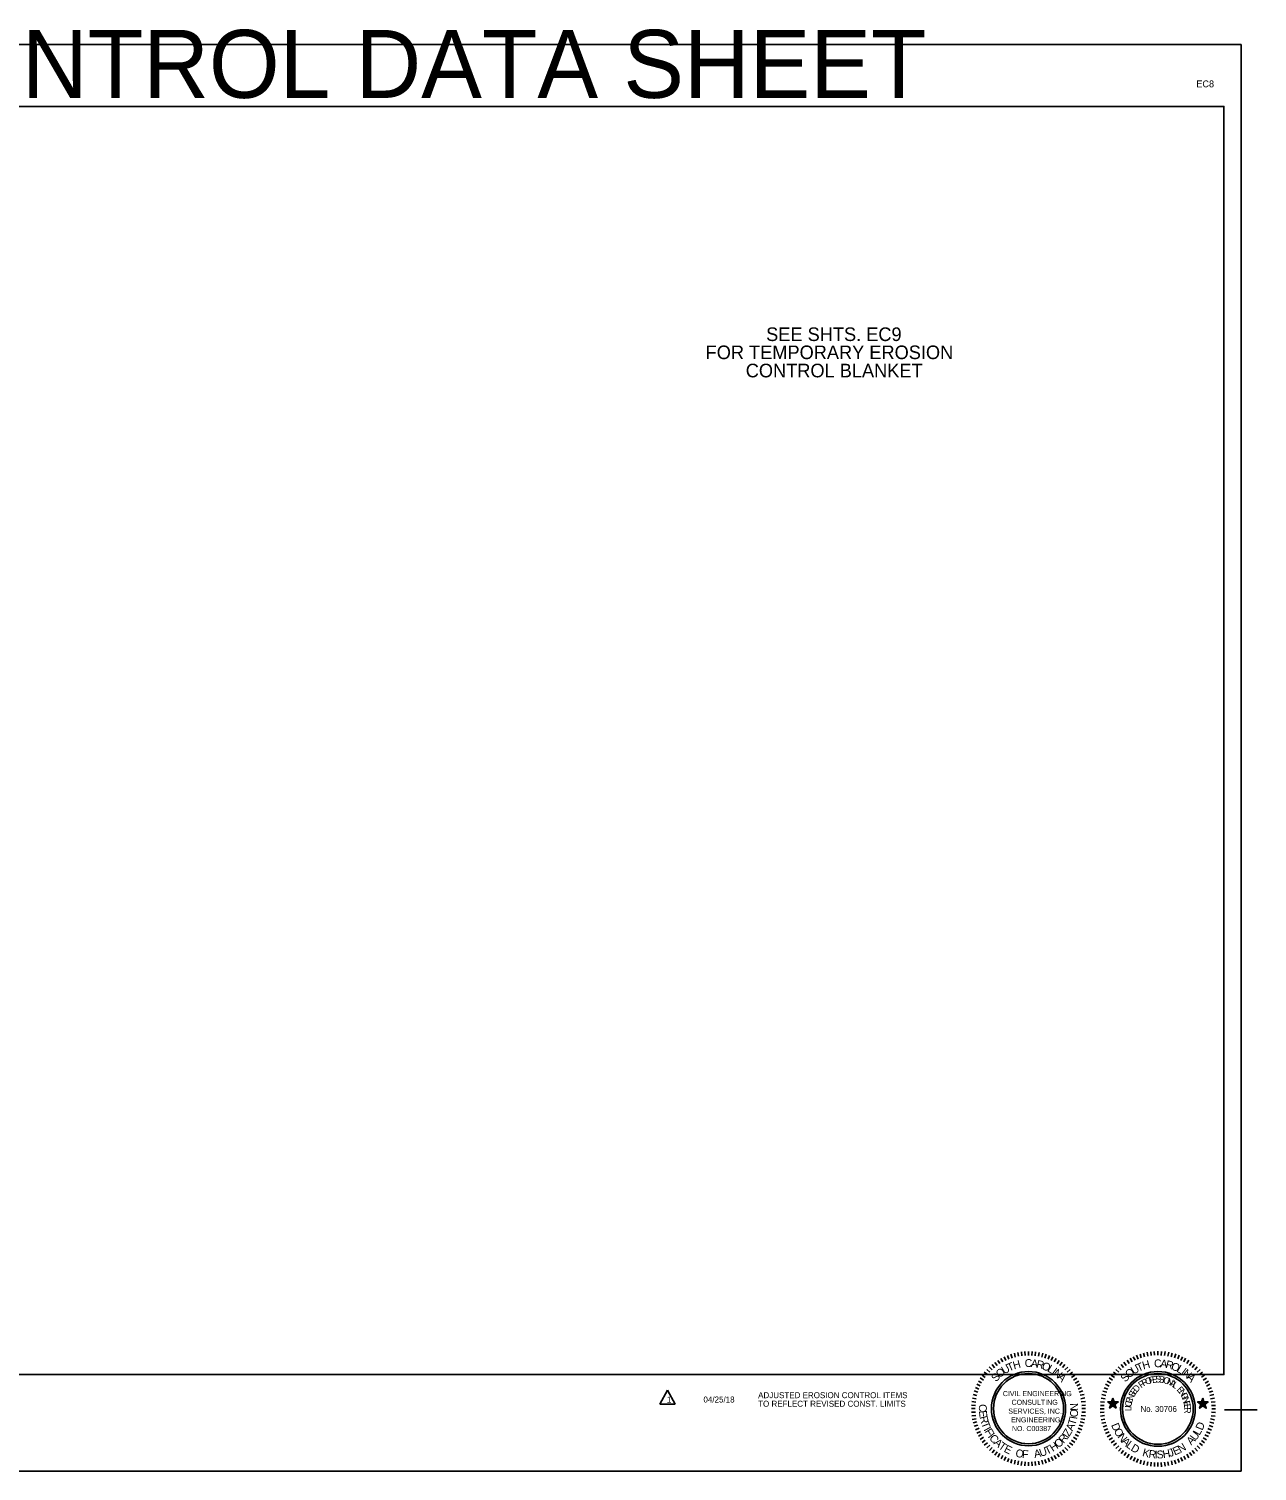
# Model space of a CAD drawing. Extents: x 260980 to 265883, y 322333 to 323618.
# Drawn here: x 261883 to 262786, y 322333 to 323393 of the extents above; entities that cross this region are included whole.
import ezdxf

# ---------------------------------------------------------------- set-up
doc = ezdxf.new("R2010")
doc.units = 0
for name, color, linetype in [('Level 23', 7, 'Continuous'), ('Level 3', 7, 'Continuous'), ('Level 4', 7, 'Continuous'), ('Level 8', 7, 'Continuous'), ('RD_SHT_SEAL_KA', 7, 'Continuous'), ('RD_SHT_TX', 7, 'Continuous')]:
    doc.layers.add(name, color=color, linetype=linetype)

msp = doc.modelspace()

# ---------------------------------------------------------------- linework, layer by layer
at = {"layer": 'Level 23'}
msp.add_lwpolyline([(261111.1, 323336.4), (262761.5, 323336.4), (262761.5, 322403.8), (261111.1, 322403.8)], close=True, dxfattribs=at)
at = {"layer": 'Level 3'}
for p, q in [((261099.2, 323381.9), (262774.2, 323381.9)), ((262774.2, 322332.8), (262774.2, 323381.9)), ((261099.2, 322332.9), (262774.2, 322332.9))]:
    msp.add_line(p, q, dxfattribs=at)
msp.add_lwpolyline([(261111.1, 322403.8), (262761.5, 322403.8), (262761.5, 323336.4), (261111.1, 323336.4)], close=True, dxfattribs=at)
at = {"layer": 'Level 4'}
msp.add_line((262762, 322377.8), (262786, 322377.8), dxfattribs=at)
at = {"layer": 'RD_SHT_SEAL_KA'}
for p, q in [((262600, 322416.8), (262601.2, 322414.2)), ((262602.4, 322417.9), (262603.5, 322415.2)), ((262604.9, 322418.8), (262605.8, 322416)), ((262607.5, 322419.5), (262608.1, 322416.7)), ((262610.1, 322420.2), (262610.5, 322417.3)), ((262612.7, 322420.5), (262613, 322417.7)), ((262615.3, 322420.8), (262615.4, 322417.9)), ((262617.9, 322420.9), (262617.9, 322418)), ((262620.6, 322420.8), (262620.4, 322417.9)), ((262623.1, 322420.5), (262622.8, 322417.7)), ((262625.7, 322420.1), (262625.3, 322417.4)), ((262628.4, 322419.5), (262627.6, 322416.7)), ((262630.9, 322418.8), (262630, 322416)), ((262633.3, 322417.9), (262632.4, 322415.2)), ((262635.8, 322416.8), (262634.6, 322414.2)), ((262692.5, 322415.8), (262694, 322413.2)), ((262694.9, 322417), (262696.2, 322414.4)), ((262697.4, 322418.1), (262698.5, 322415.3)), ((262699.9, 322418.9), (262700.8, 322416.2)), ((262702.4, 322419.7), (262703.1, 322416.9)), ((262705.1, 322420.3), (262705.6, 322417.4)), ((262707.7, 322420.6), (262708.1, 322417.8)), ((262710.3, 322420.9), (262710.5, 322418.1)), ((262713, 322421), (262713, 322418.2)), ((262715.6, 322420.9), (262715.4, 322417.9)), ((262718.3, 322420.7), (262717.9, 322417.8)), ((262721, 322420.3), (262720.4, 322417.5)), ((262723.6, 322419.7), (262722.8, 322416.9)), ((262726.1, 322419), (262725.2, 322416.2)), ((262728.6, 322418.1), (262727.6, 322415.4)), ((262731, 322417), (262729.8, 322414.3)), ((262733.4, 322415.8), (262732, 322413.3)), ((262585.4, 322405.6), (262587.7, 322403.8)), ((262587.3, 322407.5), (262589.4, 322405.6)), ((262589, 322409.5), (262591.1, 322407.4)), ((262591.1, 322411.3), (262592.9, 322408.9)), ((262593.2, 322412.8), (262594.8, 322410.6)), ((262595.4, 322414.3), (262596.9, 322411.9)), ((262597.6, 322415.7), (262599, 322413.1)), ((262638.1, 322415.7), (262636.7, 322413.2)), ((262640.5, 322414.2), (262638.9, 322411.8)), ((262642.6, 322412.9), (262640.9, 322410.5)), ((262644.7, 322411.2), (262642.9, 322409)), ((262646.7, 322409.4), (262644.7, 322407.4)), ((262648.6, 322407.6), (262646.4, 322405.6)), ((262650.3, 322405.6), (262648.1, 322403.8)), ((262680.3, 322405.6), (262682.5, 322403.8)), ((262682.1, 322407.5), (262684.2, 322405.6)), ((262683.9, 322409.5), (262686, 322407.4)), ((262685.9, 322411.3), (262687.8, 322409)), ((262688, 322412.9), (262689.8, 322410.6)), ((262690.3, 322414.4), (262691.8, 322412)), ((262735.8, 322414.4), (262734.2, 322412)), ((262737.9, 322412.9), (262736.3, 322410.5)), ((262740, 322411.3), (262738.2, 322409.1)), ((262742, 322409.5), (262740.1, 322407.4)), ((262744, 322407.6), (262741.8, 322405.6)), ((262745.7, 322405.6), (262743.5, 322403.8)), ((262579.8, 322396.7), (262582.4, 322395.5)), ((262581.1, 322399), (262583.4, 322397.7)), ((262582.3, 322401.4), (262584.9, 322399.8)), ((262583.9, 322403.5), (262586.1, 322401.8)), ((262651.9, 322403.5), (262649.6, 322401.8)), ((262653.4, 322401.3), (262651, 322399.8)), ((262654.9, 322399.1), (262652.2, 322397.6)), ((262655.9, 322396.7), (262653.4, 322395.5)), ((262674.6, 322396.7), (262677.2, 322395.4)), ((262675.8, 322399), (262678.4, 322397.6)), ((262677.2, 322401.4), (262679.7, 322399.8)), ((262678.6, 322403.5), (262681.1, 322401.8)), ((262747.3, 322403.5), (262745, 322401.9)), ((262748.8, 322401.3), (262746.4, 322399.8)), ((262750.2, 322399), (262747.7, 322397.6)), ((262751.3, 322396.7), (262748.8, 322395.4)), ((262576.1, 322384), (262579.1, 322383.6)), ((262576.6, 322386.6), (262579.4, 322386.1)), ((262577.2, 322389.2), (262579.9, 322388.4)), ((262577.9, 322391.8), (262580.7, 322390.9)), ((262578.8, 322394.3), (262581.4, 322393.2)), ((262656.9, 322394.3), (262654.3, 322393.2)), ((262657.9, 322391.8), (262655.2, 322390.9)), ((262658.7, 322389.2), (262655.8, 322388.6)), ((262659.2, 322386.7), (262656.4, 322386.1)), ((262659.7, 322384.1), (262656.7, 322383.7)), ((262671.3, 322386.5), (262674.2, 322386)), ((262671.9, 322389.1), (262674.7, 322388.4)), ((262672.6, 322391.7), (262675.4, 322390.8)), ((262673.6, 322394.2), (262676.3, 322393.1)), ((262752.5, 322394.2), (262749.8, 322393.2)), ((262753.4, 322391.7), (262750.6, 322390.8)), ((262754.1, 322389.2), (262751.3, 322388.5)), ((262754.7, 322386.6), (262751.8, 322386)), ((262575.9, 322376.1), (262578.8, 322376.3)), ((262576, 322381.3), (262578.8, 322381.2)), ((262576, 322378.8), (262578.7, 322378.8)), ((262576.2, 322373.5), (262579.1, 322373.8)), ((262659.7, 322373.5), (262656.7, 322373.8)), ((262659.9, 322381.4), (262657, 322381.2)), ((262659.9, 322376.1), (262657, 322376.3)), ((262659.9, 322378.8), (262657.1, 322378.8)), ((262670.6, 322378.6), (262673.5, 322378.6)), ((262670.6, 322375.9), (262673.5, 322376.1)), ((262670.7, 322381.2), (262673.6, 322381.1)), ((262670.9, 322383.9), (262673.8, 322383.6)), ((262670.9, 322373.2), (262673.8, 322373.7)), ((262755.2, 322383.9), (262752.2, 322383.6)), ((262755, 322373.3), (262752.2, 322373.6)), ((262755.3, 322381.2), (262752.5, 322381.1)), ((262755.3, 322376), (262752.5, 322376.2)), ((262755.4, 322378.6), (262752.6, 322378.6)), ((262576.5, 322370.9), (262579.4, 322371.4)), ((262577.2, 322368.3), (262579.9, 322369)), ((262577.9, 322365.8), (262580.6, 322366.6)), ((262578.8, 322363.2), (262581.5, 322364.4)), ((262657, 322363.3), (262654.3, 322364.4)), ((262657.9, 322365.8), (262655.1, 322366.6)), ((262658.7, 322368.3), (262655.9, 322369)), ((262659.2, 322370.8), (262656.3, 322371.4)), ((262671.3, 322370.6), (262674.1, 322371.1)), ((262671.9, 322368), (262674.7, 322368.7)), ((262672.7, 322365.5), (262675.4, 322366.4)), ((262673.5, 322363), (262676.3, 322364)), ((262752.5, 322363), (262749.7, 322364.1)), ((262753.3, 322365.5), (262750.6, 322366.4)), ((262754.1, 322368.1), (262751.3, 322368.8)), ((262754.7, 322370.6), (262751.8, 322371.2)), ((262579.8, 322360.8), (262582.5, 322362.1)), ((262581.1, 322358.5), (262583.5, 322360)), ((262582.4, 322356.2), (262584.9, 322357.8)), ((262583.9, 322353.9), (262586.1, 322355.7)), ((262585.4, 322352), (262587.7, 322353.7)), ((262650.4, 322351.9), (262648.1, 322353.7)), ((262651.9, 322353.9), (262649.6, 322355.7)), ((262653.5, 322356.1), (262650.9, 322357.7)), ((262654.7, 322358.5), (262652.2, 322359.9)), ((262655.9, 322360.9), (262653.4, 322362.1)), ((262674.6, 322360.5), (262677.2, 322361.8)), ((262675.8, 322358.1), (262678.4, 322359.6)), ((262677.2, 322355.8), (262679.6, 322357.4)), ((262678.7, 322353.6), (262681, 322355.4)), ((262680.3, 322351.6), (262682.6, 322353.4)), ((262745.8, 322351.6), (262743.5, 322353.4)), ((262747.3, 322353.6), (262745, 322355.3)), ((262748.8, 322355.8), (262746.4, 322357.3)), ((262750.2, 322358.2), (262747.6, 322359.5)), ((262751.4, 322360.5), (262748.8, 322361.8)), ((262587.3, 322350), (262589.4, 322351.9)), ((262589.1, 322348.1), (262591.1, 322350.2)), ((262591.1, 322346.3), (262592.9, 322348.5)), ((262593.2, 322344.7), (262594.9, 322347)), ((262595.3, 322343.2), (262596.9, 322345.7)), ((262597.7, 322341.9), (262599, 322344.3)), ((262600, 322340.6), (262601.2, 322343.4)), ((262602.4, 322339.6), (262603.5, 322342.2)), ((262604.9, 322338.7), (262605.7, 322341.5)), ((262633.4, 322339.6), (262632.3, 322342.3)), ((262635.9, 322340.7), (262634.6, 322343.3)), ((262638.2, 322341.9), (262636.8, 322344.3)), ((262640.4, 322343.3), (262638.9, 322345.6)), ((262642.6, 322344.7), (262640.9, 322347)), ((262644.6, 322346.3), (262642.9, 322348.5)), ((262646.7, 322348.1), (262644.7, 322350.2)), ((262648.6, 322350), (262646.5, 322351.9)), ((262682.1, 322349.5), (262684.2, 322351.5)), ((262684, 322347.6), (262685.9, 322349.7)), ((262686, 322345.9), (262687.8, 322348.1)), ((262688.1, 322344.3), (262689.8, 322346.6)), ((262690.2, 322342.7), (262691.8, 322345.2)), ((262692.6, 322341.4), (262694, 322343.9)), ((262695, 322340.2), (262696.2, 322342.8)), ((262697.3, 322339.1), (262698.5, 322341.8)), ((262728.6, 322339.1), (262727.6, 322341.8)), ((262731.1, 322340.2), (262729.9, 322342.8)), ((262733.4, 322341.4), (262732, 322343.9)), ((262735.7, 322342.7), (262734.2, 322345.2)), ((262738, 322344.3), (262736.3, 322346.6)), ((262740, 322345.9), (262738.2, 322348.1)), ((262742.1, 322347.6), (262740.1, 322349.8)), ((262743.9, 322349.5), (262741.9, 322351.5)), ((262607.5, 322338), (262608.1, 322340.8)), ((262610, 322337.4), (262610.5, 322340.3)), ((262612.6, 322336.9), (262613, 322339.9)), ((262615.3, 322336.7), (262615.5, 322339.7)), ((262617.9, 322336.7), (262617.9, 322339.5)), ((262620.6, 322336.7), (262620.4, 322339.7)), ((262623.1, 322337), (262622.8, 322339.9)), ((262625.7, 322337.4), (262625.3, 322340.2)), ((262628.3, 322338), (262627.7, 322340.8)), ((262630.9, 322338.7), (262630, 322341.4)), ((262699.9, 322338.2), (262700.7, 322341)), ((262702.4, 322337.4), (262703.1, 322340.3)), ((262705, 322336.9), (262705.6, 322339.8)), ((262707.7, 322336.5), (262708.1, 322339.4)), ((262710.4, 322336.2), (262710.5, 322339.1)), ((262713, 322336.2), (262713, 322339.1)), ((262715.7, 322336.1), (262715.5, 322339.2)), ((262718.3, 322336.5), (262717.9, 322339.4)), ((262720.9, 322336.9), (262720.4, 322339.8)), ((262723.6, 322337.5), (262722.9, 322340.3)), ((262726.1, 322338.2), (262725.2, 322340.9))]:
    msp.add_line(p, q, dxfattribs=at)
for points in [[(262679.9, 322386.5), (262679, 322383.7), (262676.1, 322383.7), (262678.5, 322381.9), (262677.5, 322379.2), (262680, 322380.9), (262682.3, 322379.2), (262681.4, 322381.9), (262683.8, 322383.7), (262680.8, 322383.7)], [(262679.9, 322386.1), (262679.1, 322383.6), (262676.4, 322383.6), (262678.5, 322382), (262677.8, 322379.4), (262679.9, 322381.1), (262682, 322379.4), (262681.2, 322382), (262683.4, 322383.6), (262680.8, 322383.6)], [(262680, 322385.7), (262679.1, 322383.4), (262676.8, 322383.4), (262678.7, 322382), (262678, 322379.8), (262679.9, 322381.2), (262681.9, 322379.7), (262681.1, 322382.1), (262683.1, 322383.4), (262680.7, 322383.4)], [(262680, 322385.3), (262679.2, 322383.3), (262677.2, 322383.3), (262678.9, 322382.1), (262678.3, 322380.1), (262679.9, 322381.3), (262681.7, 322380.1), (262681.1, 322382.1), (262682.7, 322383.4), (262680.6, 322383.3)], [(262679.9, 322385), (262679.4, 322383.2), (262677.6, 322383.2), (262679, 322382.1), (262678.4, 322380.4), (262679.9, 322381.5), (262681.4, 322380.4), (262680.8, 322382.1), (262682.3, 322383.2), (262680.6, 322383.2)], [(262679.9, 322384.6), (262679.5, 322383.1), (262677.9, 322383.1), (262679.2, 322382.2), (262678.7, 322380.7), (262680, 322381.7), (262681.2, 322380.7), (262680.7, 322382.2), (262682, 322383), (262680.4, 322383.1)], [(262679.9, 322384.1), (262679.6, 322383), (262678.3, 322382.8), (262679.3, 322382.3), (262679, 322381.1), (262679.9, 322381.8), (262681, 322381), (262680.6, 322382.3), (262681.5, 322383), (262680.3, 322383)], [(262746.1, 322386.5), (262745.1, 322383.7), (262742.2, 322383.7), (262744.6, 322381.9), (262743.6, 322379.1), (262746.1, 322380.9), (262748.5, 322379.1), (262747.5, 322381.9), (262749.9, 322383.7), (262746.9, 322383.7)], [(262746, 322386.1), (262745.2, 322383.6), (262742.6, 322383.6), (262744.8, 322381.9), (262744, 322379.4), (262746.1, 322381), (262748.2, 322379.4), (262747.4, 322382), (262749.6, 322383.6), (262746.9, 322383.6)], [(262746.1, 322385.7), (262745.4, 322383.4), (262742.9, 322383.4), (262744.9, 322382), (262744.2, 322379.7), (262746.1, 322381.2), (262748, 322379.8), (262747.3, 322382), (262749.2, 322383.5), (262746.8, 322383.4)], [(262746, 322385.3), (262745.4, 322383.3), (262743.3, 322383.3), (262745.1, 322382.1), (262744.3, 322380.1), (262746.1, 322381.3), (262747.8, 322380.1), (262747.1, 322382.1), (262748.8, 322383.3), (262746.7, 322383.3)], [(262746, 322384.9), (262745.5, 322383.2), (262743.6, 322383.2), (262745.1, 322382.2), (262744.6, 322380.4), (262746, 322381.4), (262747.5, 322380.4), (262747, 322382.1), (262748.5, 322383.2), (262746.6, 322383.2)], [(262746.1, 322384.5), (262745.6, 322383.1), (262744, 322383.1), (262745.3, 322382.3), (262744.8, 322380.7), (262746.1, 322381.6), (262747.3, 322380.7), (262746.9, 322382.1), (262748, 322383.1), (262746.6, 322383.1)], [(262746.1, 322384.1), (262745.6, 322383), (262744.4, 322383), (262745.5, 322382.2), (262745.1, 322381.1), (262746.1, 322381.8), (262747.1, 322381), (262746.7, 322382.3), (262747.8, 322383), (262746.5, 322383)], [(262679.9, 322383.8), (262679.7, 322382.8), (262678.7, 322382.8), (262679.5, 322382.3), (262679.2, 322381.4), (262679.9, 322381.9), (262680.7, 322381.3), (262680.5, 322382.3), (262681.2, 322382.8), (262680.2, 322382.9)], [(262679.9, 322383.3), (262679.7, 322382.7), (262679, 322382.7), (262679.6, 322382.3), (262679.4, 322381.7), (262680, 322382.1), (262680.4, 322381.7), (262680.3, 322382.3), (262680.8, 322382.7), (262680.1, 322382.7)], [(262680, 322383), (262679.8, 322382.6), (262679.4, 322382.6), (262679.8, 322382.4), (262679.6, 322382), (262680, 322382.3), (262680.2, 322382), (262680.1, 322382.4), (262680.4, 322382.6), (262680.1, 322382.6)], [(262680, 322382.6), (262679.9, 322382.4), (262679.7, 322382.5), (262679.9, 322382.5), (262679.8, 322382.3), (262679.9, 322382.3), (262680, 322382.3), (262680, 322382.4), (262680.1, 322382.5), (262680, 322382.5)], [(262746.1, 322383.7), (262745.8, 322382.8), (262744.8, 322382.8), (262745.6, 322382.3), (262745.3, 322381.4), (262746.1, 322381.9), (262746.8, 322381.3), (262746.6, 322382.3), (262747.3, 322382.8), (262746.3, 322382.8)], [(262746.1, 322383.4), (262745.8, 322382.7), (262745.2, 322382.7), (262745.7, 322382.4), (262745.5, 322381.7), (262746.1, 322382), (262746.6, 322381.7), (262746.4, 322382.3), (262747, 322382.7), (262746.3, 322382.7)], [(262746, 322383), (262746, 322382.6), (262745.5, 322382.6), (262745.9, 322382.4), (262745.7, 322382), (262746.1, 322382.2), (262746.4, 322382), (262746.2, 322382.3), (262746.6, 322382.6), (262746.2, 322382.6)], [(262746.1, 322382.6), (262746.1, 322382.5), (262745.9, 322382.5), (262746, 322382.4), (262746, 322382.3), (262746, 322382.4), (262746.2, 322382.4), (262746.1, 322382.4), (262746.2, 322382.5), (262746.1, 322382.4)]]:
    msp.add_lwpolyline(points, close=True, dxfattribs=at)
for radius in [27.5, 26]:
    msp.add_circle((262713, 322378.6), radius, dxfattribs=at)
for major_axis in [(0, 27.3), (0, 25.8)]:
    msp.add_ellipse((262617.9, 322378.8), major_axis=major_axis, ratio=0.998589, dxfattribs=at)
at = {"layer": 'RD_SHT_TX'}
for p, q in [((262352.5, 322392.3), (262346.8, 322382.1)), ((262358.2, 322382.1), (262352.5, 322392.3)), ((262346.8, 322382.1), (262358.2, 322382.1))]:
    msp.add_line(p, q, dxfattribs=at)

# ---------------------------------------------------------------- texts
at = {"layer": 'Level 3'}
for s, height, p in [('EC8', 5, (262741.3, 323350.5)), ('SEE SHTS. EC9', 10, (262425, 323163.9)), ('FOR TEMPORARY EROSION', 10, (262380.5, 323150.6)), ('CONTROL BLANKET', 10, (262410, 323137.2))]:
    msp.add_text(s, height=height, dxfattribs=at).set_placement(p)
at = {"layer": 'Level 8'}
msp.add_text('EROSION CONTROL DATA SHEET', height=50, dxfattribs=at).set_placement((261450.7, 323342.7))
at = {"layer": 'RD_SHT_SEAL_KA'}
for s, height, rotation, p in [('O', 5.79, 39.0332, (262596.7, 322401.1)), ('U', 5.79, 30.8031, (262600.1, 322403.9)), ('T', 5.79, 23.2887, (262603.6, 322406)), ('H', 5.79, 15.7743, (262607.3, 322407.6)), ('C', 5.79, 0.6858, (262615.1, 322409.4)), ('A', 5.79, 352.8136, (262619.4, 322409.5)), ('R', 5.79, 345.657, (262623.2, 322409.1)), ('O', 5.79, 338.1426, (262627.1, 322408.1)), ('L', 5.79, 329.9125, (262631.2, 322406.5)), ('I', 5.79, 323.1138, (262634.4, 322404.7)), ('N', 5.79, 320.609, (262635.5, 322404)), ('O', 5.79, 39.0332, (262691.8, 322400.9)), ('U', 5.79, 30.8031, (262695.2, 322403.7)), ('T', 5.79, 23.2887, (262698.7, 322405.8)), ('H', 5.79, 15.7743, (262702.4, 322407.5)), ('C', 5.79, 0.6858, (262710.2, 322409.2)), ('A', 5.79, 352.8136, (262714.5, 322409.3)), ('R', 5.79, 345.657, (262718.3, 322408.9)), ('O', 5.79, 338.1426, (262722.2, 322407.9)), ('L', 5.79, 329.9125, (262726.3, 322406.3)), ('I', 5.79, 323.1138, (262729.5, 322404.6)), ('N', 5.79, 320.609, (262730.6, 322403.8)), ('S', 5.79, 46.5476, (262594, 322398.1)), ('A', 5.79, 313.0946, (262638.7, 322401.5)), ('S', 5.79, 46.5476, (262689.1, 322397.9)), ('D', 4.82, 48.9361, (262697.5, 322390.4)), ('P', 4.82, 35.3308, (262700.7, 322393.7)), ('R', 4.82, 28.555, (262702.5, 322395)), ('O', 4.82, 21.7793, (262704.6, 322396.1)), ('F', 4.82, 14.3582, (262706.9, 322397.1)), ('E', 4.82, 7.9051, (262709, 322397.6)), ('S', 4.82, 1.452, (262711.2, 322398)), ('S', 4.82, 354.6762, (262713.5, 322398)), ('I', 4.82, 347.9004, (262715.8, 322397.8)), ('O', 4.82, 345.6418, (262716.5, 322397.7)), ('N', 4.82, 338.2207, (262719, 322397.1)), ('A', 4.82, 331.445, (262721.1, 322396.3)), ('L', 4.82, 324.9919, (262723, 322395.2)), ('E', 4.82, 312.0319, (262726.5, 322392.5)), ('A', 5.79, 313.0946, (262733.8, 322401.3)), ('CIVIL ENGINEERING', 3.751, 359.9897, (262599, 322388)), ('CONSULTING', 3.75, 359.9897, (262605.4, 322381.6)), ('C', 4.82, 82.4923, (262693.5, 322379.8)), ('E', 4.82, 75.3939, (262693.8, 322382.2)), ('N', 4.82, 68.9407, (262694.4, 322384.3)), ('S', 4.82, 62.165, (262695.2, 322386.5)), ('E', 4.82, 55.3892, (262696.2, 322388.5)), ('N', 4.82, 305.5788, (262728, 322390.9)), ('G', 4.82, 298.803, (262729.4, 322389.1)), ('I', 4.82, 291.7046, (262730.5, 322387)), ('N', 4.82, 289.446, (262730.8, 322386.3)), ('E', 4.82, 282.6702, (262731.6, 322384.1)), ('C', 5.79, 268.515, (262581.5, 322382.2)), ('E', 5.79, 276.3872, (262581.4, 322377.2)), ('R', 5.79, 283.5438, (262581.9, 322372.7)), ('SERVICES, INC.', 3.751, 359.9897, (262603, 322375.1)), ('O', 5.79, 83.6128, (262653.9, 322372.2)), ('N', 5.79, 91.8428, (262654.4, 322377.4)), ('L', 4.82, 90.8813, (262693.6, 322377)), ('I', 4.82, 84.7509, (262693.5, 322379.1)), ('E', 4.82, 276.2171, (262732.1, 322382)), ('R', 4.82, 269.764, (262732.4, 322379.8)), ('T', 5.79, 291.0582, (262583, 322368)), ('I', 5.79, 298.5727, (262584.7, 322363.5)), ('F', 5.79, 301.0775, (262585.4, 322362.1)), ('ENGINEERING', 3.751, 359.9897, (262605.1, 322368.7)), ('NO. C00387', 3.75, 359.9897, (262605.7, 322362.3)), ('Z', 5.79, 58.9225, (262647.8, 322357.8)), ('A', 5.79, 66.437, (262650.3, 322361.9)), ('T', 5.79, 73.5935, (262652.2, 322366.1)), ('I', 5.79, 81.108, (262653.5, 322370.7)), ('D', 5.78, 292.563, (262678.5, 322366.8)), ('O', 5.78, 300.0892, (262680.3, 322362.4)), ('D', 5.78, 67.437, (262745.7, 322362.4)), ('I', 5.79, 308.234, (262587.7, 322358.2)), ('C', 5.79, 310.7388, (262588.6, 322356.9)), ('A', 5.79, 318.6111, (262591.9, 322353.1)), ('T', 5.79, 325.7677, (262595.3, 322350)), ('E', 5.79, 333.2821, (262599.3, 322347.3)), ('H', 5.79, 33.1588, (262635.7, 322346.9)), ('O', 5.79, 40.6733, (262639.8, 322349.5)), ('R', 5.79, 48.9033, (262643.7, 322352.9)), ('I', 5.79, 56.4177, (262646.9, 322356.5)), ('N', 5.78, 308.3321, (262683, 322357.9)), ('A', 5.78, 315.8583, (262685.9, 322354.1)), ('L', 5.78, 323.0261, (262689.2, 322351)), ('D', 5.78, 329.8355, (262692.6, 322348.3)), ('N', 5.78, 30.8215, (262729.6, 322346.1)), ('A', 5.78, 45.9336, (262737.5, 322351.6)), ('U', 5.78, 53.1014, (262740.7, 322354.8)), ('L', 5.78, 60.6276, (262743.5, 322358.7)), ('O', 5.79, 348.0127, (262607.9, 322343.6)), ('F', 5.79, 356.2428, (262613, 322342.6)), ('A', 5.79, 10.9734, (262622.4, 322342.5)), ('U', 5.79, 18.13, (262626.9, 322343.3)), ('T', 5.79, 25.6444, (262631.4, 322344.8)), ('K', 5.78, 344.9476, (262701.2, 322344.1)), ('R', 5.78, 352.4738, (262705.9, 322342.8)), ('I', 5.78, 360, (262710.6, 322342.2)), ('S', 5.78, 2.5087, (262712.2, 322342.1)), ('H', 5.78, 10.0349, (262717, 322342.3)), ('J', 5.78, 17.5611, (262721.7, 322343.2)), ('E', 5.78, 23.6537, (262725.4, 322344.3))]:
    msp.add_text(s, height=height, rotation=rotation, dxfattribs=at).set_placement(p)
msp.add_text('No. 30706', height=4.34, dxfattribs=at).set_placement((262700.2, 322376.4))
at = {"layer": 'RD_SHT_TX'}
for s, p in [('1', (262352, 322383.3)), ('04/25/18', (262378.9, 322383.3)), ('ADJUSTED EROSION CONTROL ITEMS ', (262419.1, 322386.5)), ('TO REFLECT REVISED CONST. LIMITS', (262419.1, 322380.2))]:
    msp.add_text(s, height=4.4, rotation=0.0016, dxfattribs=at).set_placement(p)

doc.saveas('drawing.dxf')
